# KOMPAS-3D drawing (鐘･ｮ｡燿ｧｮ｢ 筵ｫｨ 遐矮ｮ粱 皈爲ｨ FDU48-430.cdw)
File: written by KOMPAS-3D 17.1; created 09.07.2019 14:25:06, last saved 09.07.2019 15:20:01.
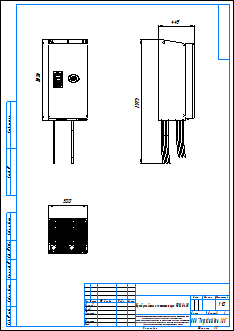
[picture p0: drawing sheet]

Sheet 1: A3, portrait

Title block, sheet 1: name: Преобразователи частоты серии FDU48-430; sheets: 1; sheet format: A3; stored path: \\adlc.lan\data\АДЛ_ПКД\3D-модели\Поставщики\Оборудование Emotron\Преобразователи частоты\Серия FDU 2.0\KOMPAS 2D\Преобразователи частоты серии FDU48-430.cdw

Views: Вид 1
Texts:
  user
  CONTINUOUS_RGB_0_0_0_THICK_0.18
  POLYLINE_STYLE_0.18_RGB_0_0_0
  Рама для чертежей
  Лит-Масса-Масштаб
  Материал-Предприятие
  Масштаб
  Изм.
  Лист
  № докум.
  Подп.
  Дата
  Лит.
  Разраб.
  Пров.
  Т.контр.
  Листов
  Внимание! Данный продукт является объектом авторского права ООО «Торговый Дом АДЛ».
  Запрещается изменение, копирование, распространение
  (в том числе путем копирования на другие сайты и ресурсы в Интернете)
  или любое иное использование информации и объектов без предварительного
  согласия правообладателя (ООО «Торговый Дом АДЛ»).
  Н.контр.
  Утв.
  ООО "Торговый дом АДЛ"
  Изменение
  Номер документа
  Подпись
  Обозначение документа
  Наименование изделия
  Масса изделия по ГОСТ 2.109-73
  Порядковый номер листа
  Общее количество листов в документе
  Характер работы, выполненной лицом, подписавшим документ
  Наименование или индекс предприятия, выпускающего документ
  Инв. № подл.
  Подп. и дата
  Взам. инв. №
  Инв. № дубл.
  Инвентарный номер подлинника по ГОСТ 2.501-68
  Подпись принявшего подлинник в отдел технической документации
  Инвентарный номер подлинника, взамен которого выпущен данный подлинник
  Инвентарный номер дубликата по ГОСТ 2.502-68
  Подпись принявшего дубликат в отдел технической документации
  Справ. №
  Перв. примен.
  Обозначение документа, взамен или на основании которого выпущен данный документ
  Обозначение документа, в котором впервые записан данный документ
  Подпись лица, копировавшего чертеж
  Обозначение формата листа
  !Рама для чертежа
Dimensions and other numbers on the sheet: 1036; 449; 1575; 500; 1:10; 1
